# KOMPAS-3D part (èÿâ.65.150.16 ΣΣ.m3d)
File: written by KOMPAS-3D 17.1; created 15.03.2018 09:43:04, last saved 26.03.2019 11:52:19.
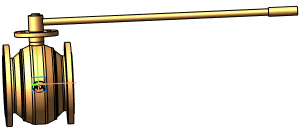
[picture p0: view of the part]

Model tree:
1. Операция без истории:4  (labels: Сталь 20  ГОСТ 1050-2013)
